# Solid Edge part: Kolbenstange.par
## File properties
Username: bmolnar
Dokumentum tartalom típus: 0
Author: bmolnar
Last saved by: bmolnar
Revision: 85
Sűrűség: 0,000 kg/m^3
Pontosság: 0,990
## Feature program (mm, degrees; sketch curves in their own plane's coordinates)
base feature "unnamed BaseFeature 1"
sketch for "unnamed Protrusion 1" plane through (-0.0012, 0, -18.75) normal (0, 0, -1) x-axis (0, -1, 0)
  circle centre (0, -0.0012) radius 25
extrude "unnamed Protrusion 1" add finite 8.3 along +normal
sketch for "Kihúzás_2" #1 plane through (-0.0012, 0, -18.75) normal (0, 0, -1) x-axis (0, -1, 0)
  circle centre (0, -0.0012) radius 8
sketch for "Kihúzás_2" #2 plane through (-0.0012, 0, -18.75) normal (0, 0, -1) x-axis (0, -1, 0)
  circle centre (0, -0.0012) radius 25
extrude "Kihúzás_2" add finite 28.8 along -normal
sketch for "Furat_1" plane through (0, 0, 61.0163) normal (0, 0, 1) x-axis (0, 1, 0)
  hole centre (0, 0) bore radius 3.3235
hole "Furat_1" nominal diameter 8 finite  VBottomAngle = 118 deg; ThreadDepth = 14.27 mm
chamfer "Letörés_1" setback 0.7  SetBackValue2 = 45 deg
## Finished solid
Body 1: solid body, 17 faces, 23 edges, 8 vertices.
  Faces by surface: plane 8, cylinder 5, cone 3, torus 1
  Edges by curve: circle 13, line 6, curve on surface 2, ellipse 2
Bounding box of the edges (mm; curved faces can reach further): 50.000 x 50.000 x 90.800, from (-25, -25, -27.05) to (25, 25, 63.75).
Cylindrical faces by radius (mm): R3.3235 x2, R4.125 x1, R8 x1, R25 x1
Conical faces (half-angle, radius in mm at the cone's reference point): 45 deg R4.0235 x1, 45 deg R4.225 x1, 59 deg R3.3235 x1
Toroidal faces (ring radius, tube radius in mm): R6.2 r1.8 x1
Planar faces by outward normal: +x 1, +z 3, -x 1, -z 1, oblique 2
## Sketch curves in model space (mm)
circle centre (0, 0, -18.75) radius 8
circle centre (0, 0, -18.75) radius 25
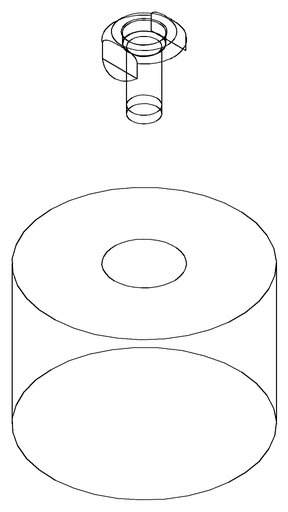
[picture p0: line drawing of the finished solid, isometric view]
